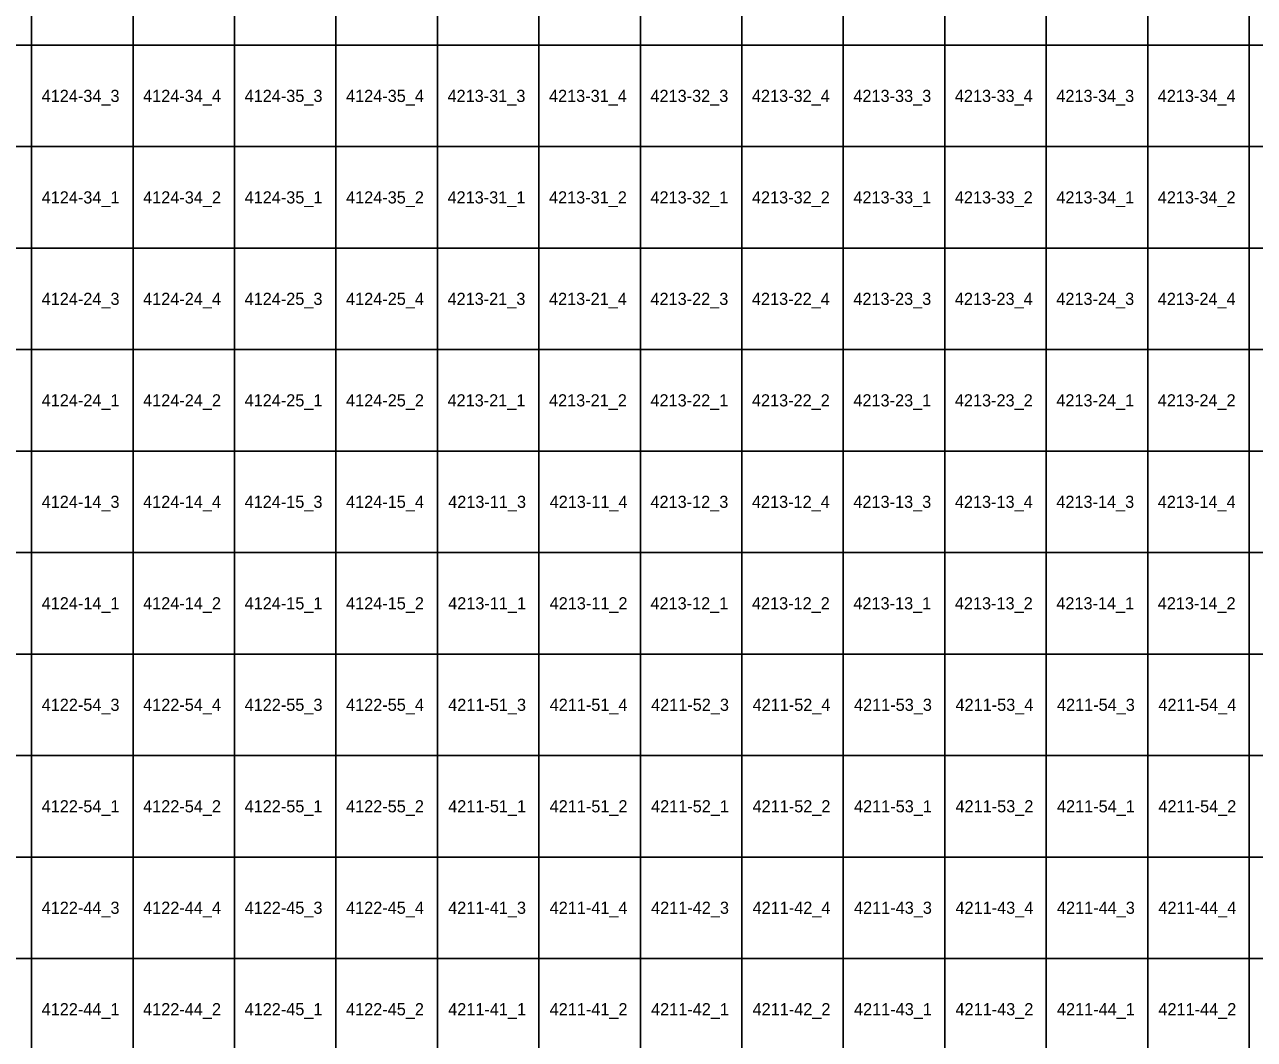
# Model space of a CAD drawing. Extents: x 312500 to 765000, y 172500 to 440000.
# Drawn here: x 389827 to 420129, y 315507 to 340507 of the extents above; entities that cross this region are included whole.
import ezdxf

# ---------------------------------------------------------------- set-up
doc = ezdxf.new("R2010")
doc.units = 0
doc.layers.add('Topo5_ramis_TKS2025', color=7, linetype='Continuous')
doc.layers.add('Topo5_ramis_TKS2025_Nr', color=7, linetype='Continuous')

msp = doc.modelspace()

# ---------------------------------------------------------------- linework, layer by layer
at = {"layer": 'Topo5_ramis_TKS2025'}
for points in [[(387500, 340000), (387500, 342500), (390000, 342500), (390000, 340000), (387500, 340000)], [(390000, 340000), (390000, 342500), (392500, 342500), (392500, 340000), (390000, 340000)], [(392500, 340000), (392500, 342500), (395000, 342500), (395000, 340000), (392500, 340000)], [(395000, 340000), (395000, 342500), (397500, 342500), (397500, 340000), (395000, 340000)], [(397500, 340000), (397500, 342500), (400000, 342500), (400000, 340000), (397500, 340000)], [(400000, 340000), (400000, 342500), (402500, 342500), (402500, 340000), (400000, 340000)], [(402500, 340000), (402500, 342500), (405000, 342500), (405000, 340000), (402500, 340000)], [(405000, 340000), (405000, 342500), (407500, 342500), (407500, 340000), (405000, 340000)], [(407500, 340000), (407500, 342500), (410000, 342500), (410000, 340000), (407500, 340000)], [(410000, 340000), (410000, 342500), (412500, 342500), (412500, 340000), (410000, 340000)], [(412500, 340000), (412500, 342500), (415000, 342500), (415000, 340000), (412500, 340000)], [(415000, 340000), (415000, 342500), (417500, 342500), (417500, 340000), (415000, 340000)], [(417500, 340000), (417500, 342500), (420000, 342500), (420000, 340000), (417500, 340000)], [(420000, 340000), (420000, 342500), (422500, 342500), (422500, 340000), (420000, 340000)], [(387500, 337500), (387500, 340000), (390000, 340000), (390000, 337500), (387500, 337500)], [(390000, 337500), (390000, 340000), (392500, 340000), (392500, 337500), (390000, 337500)], [(392500, 337500), (392500, 340000), (395000, 340000), (395000, 337500), (392500, 337500)], [(395000, 337500), (395000, 340000), (397500, 340000), (397500, 337500), (395000, 337500)], [(397500, 337500), (397500, 340000), (400000, 340000), (400000, 337500), (397500, 337500)], [(400000, 337500), (400000, 340000), (402500, 340000), (402500, 337500), (400000, 337500)], [(402500, 337500), (402500, 340000), (405000, 340000), (405000, 337500), (402500, 337500)], [(405000, 337500), (405000, 340000), (407500, 340000), (407500, 337500), (405000, 337500)], [(407500, 337500), (407500, 340000), (410000, 340000), (410000, 337500), (407500, 337500)], [(410000, 337500), (410000, 340000), (412500, 340000), (412500, 337500), (410000, 337500)], [(412500, 337500), (412500, 340000), (415000, 340000), (415000, 337500), (412500, 337500)], [(415000, 337500), (415000, 340000), (417500, 340000), (417500, 337500), (415000, 337500)], [(417500, 337500), (417500, 340000), (420000, 340000), (420000, 337500), (417500, 337500)], [(420000, 337500), (420000, 340000), (422500, 340000), (422500, 337500), (420000, 337500)], [(387500, 335000), (387500, 337500), (390000, 337500), (390000, 335000), (387500, 335000)], [(390000, 335000), (390000, 337500), (392500, 337500), (392500, 335000), (390000, 335000)], [(392500, 335000), (392500, 337500), (395000, 337500), (395000, 335000), (392500, 335000)], [(395000, 335000), (395000, 337500), (397500, 337500), (397500, 335000), (395000, 335000)], [(397500, 335000), (397500, 337500), (400000, 337500), (400000, 335000), (397500, 335000)], [(400000, 335000), (400000, 337500), (402500, 337500), (402500, 335000), (400000, 335000)], [(402500, 335000), (402500, 337500), (405000, 337500), (405000, 335000), (402500, 335000)], [(405000, 335000), (405000, 337500), (407500, 337500), (407500, 335000), (405000, 335000)], [(407500, 335000), (407500, 337500), (410000, 337500), (410000, 335000), (407500, 335000)], [(410000, 335000), (410000, 337500), (412500, 337500), (412500, 335000), (410000, 335000)], [(412500, 335000), (412500, 337500), (415000, 337500), (415000, 335000), (412500, 335000)], [(415000, 335000), (415000, 337500), (417500, 337500), (417500, 335000), (415000, 335000)], [(417500, 335000), (417500, 337500), (420000, 337500), (420000, 335000), (417500, 335000)], [(420000, 335000), (420000, 337500), (422500, 337500), (422500, 335000), (420000, 335000)], [(387500, 332500), (387500, 335000), (390000, 335000), (390000, 332500), (387500, 332500)], [(390000, 332500), (390000, 335000), (392500, 335000), (392500, 332500), (390000, 332500)], [(392500, 332500), (392500, 335000), (395000, 335000), (395000, 332500), (392500, 332500)], [(395000, 332500), (395000, 335000), (397500, 335000), (397500, 332500), (395000, 332500)], [(397500, 332500), (397500, 335000), (400000, 335000), (400000, 332500), (397500, 332500)], [(400000, 332500), (400000, 335000), (402500, 335000), (402500, 332500), (400000, 332500)], [(402500, 332500), (402500, 335000), (405000, 335000), (405000, 332500), (402500, 332500)], [(405000, 332500), (405000, 335000), (407500, 335000), (407500, 332500), (405000, 332500)], [(407500, 332500), (407500, 335000), (410000, 335000), (410000, 332500), (407500, 332500)], [(410000, 332500), (410000, 335000), (412500, 335000), (412500, 332500), (410000, 332500)], [(412500, 332500), (412500, 335000), (415000, 335000), (415000, 332500), (412500, 332500)], [(415000, 332500), (415000, 335000), (417500, 335000), (417500, 332500), (415000, 332500)], [(417500, 332500), (417500, 335000), (420000, 335000), (420000, 332500), (417500, 332500)], [(420000, 332500), (420000, 335000), (422500, 335000), (422500, 332500), (420000, 332500)], [(387500, 330000), (387500, 332500), (390000, 332500), (390000, 330000), (387500, 330000)], [(390000, 330000), (390000, 332500), (392500, 332500), (392500, 330000), (390000, 330000)], [(392500, 330000), (392500, 332500), (395000, 332500), (395000, 330000), (392500, 330000)], [(395000, 330000), (395000, 332500), (397500, 332500), (397500, 330000), (395000, 330000)], [(397500, 330000), (397500, 332500), (400000, 332500), (400000, 330000), (397500, 330000)], [(400000, 330000), (400000, 332500), (402500, 332500), (402500, 330000), (400000, 330000)], [(402500, 330000), (402500, 332500), (405000, 332500), (405000, 330000), (402500, 330000)], [(405000, 330000), (405000, 332500), (407500, 332500), (407500, 330000), (405000, 330000)], [(407500, 330000), (407500, 332500), (410000, 332500), (410000, 330000), (407500, 330000)], [(410000, 330000), (410000, 332500), (412500, 332500), (412500, 330000), (410000, 330000)], [(412500, 330000), (412500, 332500), (415000, 332500), (415000, 330000), (412500, 330000)], [(415000, 330000), (415000, 332500), (417500, 332500), (417500, 330000), (415000, 330000)], [(417500, 330000), (417500, 332500), (420000, 332500), (420000, 330000), (417500, 330000)], [(420000, 330000), (420000, 332500), (422500, 332500), (422500, 330000), (420000, 330000)], [(387500, 327500), (387500, 330000), (390000, 330000), (390000, 327500), (387500, 327500)], [(390000, 327500), (390000, 330000), (392500, 330000), (392500, 327500), (390000, 327500)], [(392500, 327500), (392500, 330000), (395000, 330000), (395000, 327500), (392500, 327500)], [(395000, 327500), (395000, 330000), (397500, 330000), (397500, 327500), (395000, 327500)], [(397500, 327500), (397500, 330000), (400000, 330000), (400000, 327500), (397500, 327500)], [(400000, 327500), (400000, 330000), (402500, 330000), (402500, 327500), (400000, 327500)], [(402500, 327500), (402500, 330000), (405000, 330000), (405000, 327500), (402500, 327500)], [(405000, 327500), (405000, 330000), (407500, 330000), (407500, 327500), (405000, 327500)], [(407500, 327500), (407500, 330000), (410000, 330000), (410000, 327500), (407500, 327500)], [(410000, 327500), (410000, 330000), (412500, 330000), (412500, 327500), (410000, 327500)], [(412500, 327500), (412500, 330000), (415000, 330000), (415000, 327500), (412500, 327500)], [(415000, 327500), (415000, 330000), (417500, 330000), (417500, 327500), (415000, 327500)], [(417500, 327500), (417500, 330000), (420000, 330000), (420000, 327500), (417500, 327500)], [(420000, 327500), (420000, 330000), (422500, 330000), (422500, 327500), (420000, 327500)], [(387500, 325000), (387500, 327500), (390000, 327500), (390000, 325000), (387500, 325000)], [(390000, 325000), (390000, 327500), (392500, 327500), (392500, 325000), (390000, 325000)], [(392500, 325000), (392500, 327500), (395000, 327500), (395000, 325000), (392500, 325000)], [(395000, 325000), (395000, 327500), (397500, 327500), (397500, 325000), (395000, 325000)], [(397500, 325000), (397500, 327500), (400000, 327500), (400000, 325000), (397500, 325000)], [(400000, 325000), (400000, 327500), (402500, 327500), (402500, 325000), (400000, 325000)], [(402500, 325000), (402500, 327500), (405000, 327500), (405000, 325000), (402500, 325000)], [(405000, 325000), (405000, 327500), (407500, 327500), (407500, 325000), (405000, 325000)], [(407500, 325000), (407500, 327500), (410000, 327500), (410000, 325000), (407500, 325000)], [(410000, 325000), (410000, 327500), (412500, 327500), (412500, 325000), (410000, 325000)], [(412500, 325000), (412500, 327500), (415000, 327500), (415000, 325000), (412500, 325000)], [(415000, 325000), (415000, 327500), (417500, 327500), (417500, 325000), (415000, 325000)], [(417500, 325000), (417500, 327500), (420000, 327500), (420000, 325000), (417500, 325000)], [(420000, 325000), (420000, 327500), (422500, 327500), (422500, 325000), (420000, 325000)], [(387500, 322500), (387500, 325000), (390000, 325000), (390000, 322500), (387500, 322500)], [(390000, 322500), (390000, 325000), (392500, 325000), (392500, 322500), (390000, 322500)], [(392500, 322500), (392500, 325000), (395000, 325000), (395000, 322500), (392500, 322500)], [(395000, 322500), (395000, 325000), (397500, 325000), (397500, 322500), (395000, 322500)], [(397500, 322500), (397500, 325000), (400000, 325000), (400000, 322500), (397500, 322500)], [(400000, 322500), (400000, 325000), (402500, 325000), (402500, 322500), (400000, 322500)], [(402500, 322500), (402500, 325000), (405000, 325000), (405000, 322500), (402500, 322500)], [(405000, 322500), (405000, 325000), (407500, 325000), (407500, 322500), (405000, 322500)], [(407500, 322500), (407500, 325000), (410000, 325000), (410000, 322500), (407500, 322500)], [(410000, 322500), (410000, 325000), (412500, 325000), (412500, 322500), (410000, 322500)], [(412500, 322500), (412500, 325000), (415000, 325000), (415000, 322500), (412500, 322500)], [(415000, 322500), (415000, 325000), (417500, 325000), (417500, 322500), (415000, 322500)], [(417500, 322500), (417500, 325000), (420000, 325000), (420000, 322500), (417500, 322500)], [(420000, 322500), (420000, 325000), (422500, 325000), (422500, 322500), (420000, 322500)], [(387500, 320000), (387500, 322500), (390000, 322500), (390000, 320000), (387500, 320000)], [(390000, 320000), (390000, 322500), (392500, 322500), (392500, 320000), (390000, 320000)], [(392500, 320000), (392500, 322500), (395000, 322500), (395000, 320000), (392500, 320000)], [(395000, 320000), (395000, 322500), (397500, 322500), (397500, 320000), (395000, 320000)], [(397500, 320000), (397500, 322500), (400000, 322500), (400000, 320000), (397500, 320000)], [(400000, 320000), (400000, 322500), (402500, 322500), (402500, 320000), (400000, 320000)], [(402500, 320000), (402500, 322500), (405000, 322500), (405000, 320000), (402500, 320000)], [(405000, 320000), (405000, 322500), (407500, 322500), (407500, 320000), (405000, 320000)], [(407500, 320000), (407500, 322500), (410000, 322500), (410000, 320000), (407500, 320000)], [(410000, 320000), (410000, 322500), (412500, 322500), (412500, 320000), (410000, 320000)], [(412500, 320000), (412500, 322500), (415000, 322500), (415000, 320000), (412500, 320000)], [(415000, 320000), (415000, 322500), (417500, 322500), (417500, 320000), (415000, 320000)], [(417500, 320000), (417500, 322500), (420000, 322500), (420000, 320000), (417500, 320000)], [(420000, 320000), (420000, 322500), (422500, 322500), (422500, 320000), (420000, 320000)], [(387500, 317500), (387500, 320000), (390000, 320000), (390000, 317500), (387500, 317500)], [(390000, 317500), (390000, 320000), (392500, 320000), (392500, 317500), (390000, 317500)], [(392500, 317500), (392500, 320000), (395000, 320000), (395000, 317500), (392500, 317500)], [(395000, 317500), (395000, 320000), (397500, 320000), (397500, 317500), (395000, 317500)], [(397500, 317500), (397500, 320000), (400000, 320000), (400000, 317500), (397500, 317500)], [(400000, 317500), (400000, 320000), (402500, 320000), (402500, 317500), (400000, 317500)], [(402500, 317500), (402500, 320000), (405000, 320000), (405000, 317500), (402500, 317500)], [(405000, 317500), (405000, 320000), (407500, 320000), (407500, 317500), (405000, 317500)], [(407500, 317500), (407500, 320000), (410000, 320000), (410000, 317500), (407500, 317500)], [(410000, 317500), (410000, 320000), (412500, 320000), (412500, 317500), (410000, 317500)], [(412500, 317500), (412500, 320000), (415000, 320000), (415000, 317500), (412500, 317500)], [(415000, 317500), (415000, 320000), (417500, 320000), (417500, 317500), (415000, 317500)], [(417500, 317500), (417500, 320000), (420000, 320000), (420000, 317500), (417500, 317500)], [(420000, 317500), (420000, 320000), (422500, 320000), (422500, 317500), (420000, 317500)], [(387500, 315000), (387500, 317500), (390000, 317500), (390000, 315000), (387500, 315000)], [(390000, 315000), (390000, 317500), (392500, 317500), (392500, 315000), (390000, 315000)], [(392500, 315000), (392500, 317500), (395000, 317500), (395000, 315000), (392500, 315000)], [(395000, 315000), (395000, 317500), (397500, 317500), (397500, 315000), (395000, 315000)], [(397500, 315000), (397500, 317500), (400000, 317500), (400000, 315000), (397500, 315000)], [(400000, 315000), (400000, 317500), (402500, 317500), (402500, 315000), (400000, 315000)], [(402500, 315000), (402500, 317500), (405000, 317500), (405000, 315000), (402500, 315000)], [(405000, 315000), (405000, 317500), (407500, 317500), (407500, 315000), (405000, 315000)], [(407500, 315000), (407500, 317500), (410000, 317500), (410000, 315000), (407500, 315000)], [(410000, 315000), (410000, 317500), (412500, 317500), (412500, 315000), (410000, 315000)], [(412500, 315000), (412500, 317500), (415000, 317500), (415000, 315000), (412500, 315000)], [(415000, 315000), (415000, 317500), (417500, 317500), (417500, 315000), (415000, 315000)], [(417500, 315000), (417500, 317500), (420000, 317500), (420000, 315000), (417500, 315000)], [(420000, 315000), (420000, 317500), (422500, 317500), (422500, 315000), (420000, 315000)]]:
    msp.add_lwpolyline(points, dxfattribs=at)

# ---------------------------------------------------------------- texts
at = {"layer": 'Topo5_ramis_TKS2025_Nr'}
for s, p in [('4124-34_3', (390248, 338600)), ('4124-34_4', (392748, 338600)), ('4124-35_3', (395248, 338600)), ('4124-35_4', (397748, 338600)), ('4213-31_3', (400248, 338600)), ('4213-31_4', (402748, 338600)), ('4213-32_3', (405248, 338600)), ('4213-32_4', (407748, 338600)), ('4213-33_3', (410248, 338600)), ('4213-33_4', (412748, 338600)), ('4213-34_3', (415248, 338600)), ('4213-34_4', (417748, 338600)), ('4124-34_1', (390248, 336100)), ('4124-34_2', (392748, 336100)), ('4124-35_1', (395248, 336100)), ('4124-35_2', (397748, 336100)), ('4213-31_1', (400248, 336100)), ('4213-31_2', (402748, 336100)), ('4213-32_1', (405248, 336100)), ('4213-32_2', (407748, 336100)), ('4213-33_1', (410248, 336100)), ('4213-33_2', (412748, 336100)), ('4213-34_1', (415248, 336100)), ('4213-34_2', (417748, 336100)), ('4124-24_3', (390248, 333600)), ('4124-24_4', (392748, 333600)), ('4124-25_3', (395248, 333600)), ('4124-25_4', (397748, 333600)), ('4213-21_3', (400248, 333600)), ('4213-21_4', (402748, 333600)), ('4213-22_3', (405248, 333600)), ('4213-22_4', (407748, 333600)), ('4213-23_3', (410248, 333600)), ('4213-23_4', (412748, 333600)), ('4213-24_3', (415248, 333600)), ('4213-24_4', (417748, 333600)), ('4124-24_1', (390248, 331100)), ('4124-24_2', (392748, 331100)), ('4124-25_1', (395248, 331100)), ('4124-25_2', (397748, 331100)), ('4213-21_1', (400248, 331100)), ('4213-21_2', (402748, 331100)), ('4213-22_1', (405248, 331100)), ('4213-22_2', (407748, 331100)), ('4213-23_1', (410248, 331100)), ('4213-23_2', (412748, 331100)), ('4213-24_1', (415248, 331100)), ('4213-24_2', (417748, 331100)), ('4124-14_3', (390248, 328600)), ('4124-14_4', (392748, 328600)), ('4124-15_3', (395248, 328600)), ('4124-15_4', (397748, 328600)), ('4213-11_3', (400264, 328600)), ('4213-11_4', (402764, 328600)), ('4213-12_3', (405248, 328600)), ('4213-12_4', (407748, 328600)), ('4213-13_3', (410248, 328600)), ('4213-13_4', (412748, 328600)), ('4213-14_3', (415248, 328600)), ('4213-14_4', (417748, 328600)), ('4124-14_1', (390248, 326100)), ('4124-14_2', (392748, 326100)), ('4124-15_1', (395248, 326100)), ('4124-15_2', (397748, 326100)), ('4213-11_1', (400264, 326100)), ('4213-11_2', (402764, 326100)), ('4213-12_1', (405248, 326100)), ('4213-12_2', (407748, 326100)), ('4213-13_1', (410248, 326100)), ('4213-13_2', (412748, 326100)), ('4213-14_1', (415248, 326100)), ('4213-14_2', (417748, 326100)), ('4122-54_3', (390248, 323600)), ('4122-54_4', (392748, 323600)), ('4122-55_3', (395248, 323600)), ('4122-55_4', (397748, 323600)), ('4211-51_3', (400264, 323600)), ('4211-51_4', (402764, 323600)), ('4211-52_3', (405264, 323600)), ('4211-52_4', (407764, 323600)), ('4211-53_3', (410264, 323600)), ('4211-53_4', (412764, 323600)), ('4211-54_3', (415264, 323600)), ('4211-54_4', (417764, 323600)), ('4122-54_1', (390248, 321100)), ('4122-54_2', (392748, 321100)), ('4122-55_1', (395248, 321100)), ('4122-55_2', (397748, 321100)), ('4211-51_1', (400264, 321100)), ('4211-51_2', (402764, 321100)), ('4211-52_1', (405264, 321100)), ('4211-52_2', (407764, 321100)), ('4211-53_1', (410264, 321100)), ('4211-53_2', (412764, 321100)), ('4211-54_1', (415264, 321100)), ('4211-54_2', (417764, 321100)), ('4122-44_3', (390248, 318600)), ('4122-44_4', (392748, 318600)), ('4122-45_3', (395248, 318600)), ('4122-45_4', (397748, 318600)), ('4211-41_3', (400264, 318600)), ('4211-41_4', (402764, 318600)), ('4211-42_3', (405264, 318600)), ('4211-42_4', (407764, 318600)), ('4211-43_3', (410264, 318600)), ('4211-43_4', (412764, 318600)), ('4211-44_3', (415264, 318600)), ('4211-44_4', (417764, 318600)), ('4122-44_1', (390248, 316100)), ('4122-44_2', (392748, 316100)), ('4122-45_1', (395248, 316100)), ('4122-45_2', (397748, 316100)), ('4211-41_1', (400264, 316100)), ('4211-41_2', (402764, 316100)), ('4211-42_1', (405264, 316100)), ('4211-42_2', (407764, 316100)), ('4211-43_1', (410264, 316100)), ('4211-43_2', (412764, 316100)), ('4211-44_1', (415264, 316100)), ('4211-44_2', (417764, 316100))]:
    msp.add_text(s, height=300, dxfattribs=at).set_placement(p)

doc.saveas('drawing.dxf')
